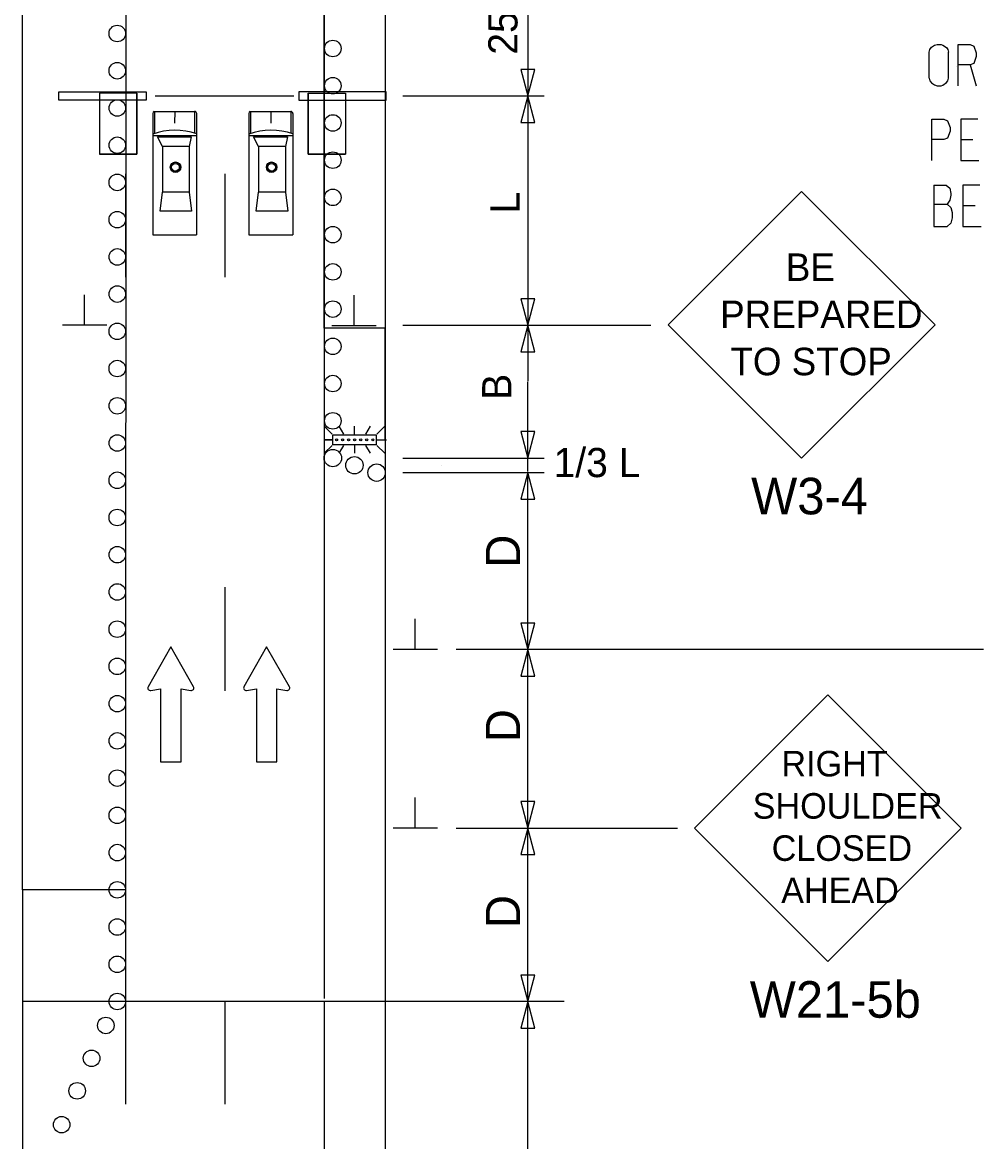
# Model space of a CAD drawing. Extents: x -1809 to 1557, y -1087 to 44.
# Drawn here: x -1476.9 to -1244.5, y -437.6 to -167 of the extents above; entities that cross this region are included whole.
import ezdxf

# ---------------------------------------------------------------- set-up
doc = ezdxf.new("R2010")
doc.units = 0
for name, color, linetype in [('BORDER', 7, 'Continuous'), ('Level 1', 7, 'Continuous'), ('Level 42', 7, 'Continuous'), ('MT_SCRATCH_LEVEL_A', 7, 'Continuous'), ('MT_SCRATCH_LEVEL_E', 7, 'Continuous'), ('MT_STAGE_1A_NOTES', 7, 'Continuous'), ('PAVT_EDGE_EX', 7, 'Continuous'), ('PAVT_EDGE_PR', 7, 'Continuous'), ('TRAFFIC_SIGNS_PR', 7, 'Continuous'), ('TYPICAL_EX', 7, 'Continuous'), ('TYPICAL_TEXT_DIMEN_EX', 7, 'Continuous'), ('TYPICAL_TEXT_DIMEN_PR', 7, 'Continuous')]:
    doc.layers.add(name, color=color, linetype=linetype)

msp = doc.modelspace()

# ---------------------------------------------------------------- linework, layer by layer
at = {"layer": 'BORDER'}
for p, q in [((-1403.94, -150.77), (-1403.94, -403.06)), ((-1451.94, -203.63), (-1451.94, -228.63)), ((-1427.94, -203.63), (-1427.94, -228.63)), ((-1451.94, -228.63), (-1451.94, -228.63)), ((-1427.94, -228.63), (-1427.94, -228.63)), ((-1451.94, -303.63), (-1451.94, -328.63)), ((-1427.94, -303.63), (-1427.94, -328.63)), ((-1451.94, -403.63), (-1451.94, -428.63)), ((-1427.94, -403.63), (-1427.94, -428.63)), ((-1403.94, -403.77), (-1403.94, -728.63))]:
    msp.add_line(p, q, dxfattribs=at)
at = {"layer": 'Level 1'}
for p, q in [((-1445.39, -189.02), (-1445.39, -218.4)), ((-1445.03, -188.56), (-1444.89, -188.56)), ((-1444.97, -188.56), (-1435.38, -188.56)), ((-1435.38, -188.56), (-1435.25, -188.56)), ((-1435.26, -188.56), (-1435.25, -188.56)), ((-1434.76, -189.11), (-1434.76, -218.4)), ((-1422.16, -189.02), (-1422.16, -218.4)), ((-1421.8, -188.56), (-1421.66, -188.56)), ((-1421.74, -188.56), (-1412.16, -188.56)), ((-1412.16, -188.56), (-1412.02, -188.56)), ((-1412.04, -188.56), (-1412.02, -188.56)), ((-1411.53, -189.11), (-1411.53, -218.4)), ((-1444.25, -194.72), (-1436.07, -194.72)), ((-1443.03, -197.08), (-1444.25, -194.72)), ((-1436.07, -194.72), (-1436.54, -197.08)), ((-1421.03, -194.72), (-1412.84, -194.72)), ((-1419.8, -197.08), (-1421.03, -194.72)), ((-1412.84, -194.72), (-1413.32, -197.08)), ((-1436.54, -197.08), (-1443.03, -197.08)), ((-1443.03, -197.08), (-1443.03, -208.13)), ((-1436.54, -197.08), (-1436.54, -208.13)), ((-1413.32, -197.08), (-1419.8, -197.08)), ((-1419.8, -197.08), (-1419.8, -208.13)), ((-1413.32, -197.08), (-1413.32, -208.13)), ((-1443.6, -212.66), (-1443.03, -208.13)), ((-1436.54, -208.13), (-1443.03, -208.13)), ((-1436.54, -208.13), (-1435.98, -212.66)), ((-1420.37, -212.66), (-1419.8, -208.13)), ((-1413.32, -208.13), (-1419.8, -208.13)), ((-1413.32, -208.13), (-1412.75, -212.66)), ((-1435.98, -212.66), (-1443.6, -212.66)), ((-1412.75, -212.66), (-1420.37, -212.66)), ((-1445.39, -218.4), (-1434.76, -218.4)), ((-1422.16, -218.4), (-1411.53, -218.4))]:
    msp.add_line(p, q, dxfattribs=at)
at = {"layer": 'Level 42'}
for p, q in [((-1380.84, -272.38), (-1380.84, -272.38)), ((-1375.61, -274.12), (-1375.61, -274.12)), ((-1370.25, -275.91), (-1370.25, -275.91))]:
    msp.add_line(p, q, dxfattribs=at)
at = {"layer": 'MT_SCRATCH_LEVEL_A'}
for p, q in [((-1476.89, -403.77), (-1476.89, -407.53)), ((-1476.89, -407), (-1476.89, -728.63))]:
    msp.add_line(p, q, dxfattribs=at)
msp.add_lwpolyline([(-1476.89, -61.73), (-1389.15, -61.73), (-1389.15, -240.97), (-1403.94, -240.97), (-1403.94, -150.77), (-1451.85, -150.77), (-1451.94, -376.78), (-1476.89, -376.78), (-1476.89, -61.73), (-1476.89, -61.73)], close=True, dxfattribs=at)
at = {"layer": 'MT_SCRATCH_LEVEL_E'}
for p, q in [((-1441.03, -318.01), (-1446.51, -327.66)), ((-1435.5, -327.66), (-1441.03, -318.01)), ((-1417.86, -318.01), (-1423.34, -327.66)), ((-1412.33, -327.66), (-1417.86, -318.01)), ((-1445.87, -328.57), (-1443.5, -328.15)), ((-1443.5, -328.15), (-1443.5, -345.83)), ((-1438.51, -345.83), (-1438.51, -328.15)), ((-1438.51, -328.15), (-1436.14, -328.57)), ((-1422.69, -328.57), (-1420.32, -328.15)), ((-1420.32, -328.15), (-1420.32, -345.83)), ((-1415.34, -345.83), (-1415.34, -328.15)), ((-1415.34, -328.15), (-1412.97, -328.57)), ((-1443.5, -345.83), (-1438.51, -345.83)), ((-1420.32, -345.83), (-1415.34, -345.83))]:
    msp.add_line(p, q, dxfattribs=at)
for centre, start, end in [((-1445.97, -327.96), 150.4248, 279.9638), ((-1436.05, -327.96), 260.0362, 29.7731), ((-1422.79, -327.96), 150.4248, 279.9638), ((-1412.87, -327.96), 260.0362, 29.7731)]:
    msp.add_arc(centre, 0.617, start, end, dxfattribs=at)
at = {"layer": 'MT_STAGE_1A_NOTES'}
for p, q in [((-1354.71, -61.78), (-1354.71, -253.81)), ((-1458.25, -184.14), (-1458.25, -198.89)), ((-1449.19, -184.14), (-1449.19, -198.89)), ((-1407.81, -184.14), (-1407.81, -198.89)), ((-1398.75, -184.14), (-1398.75, -198.89)), ((-1384.95, -184.82), (-1350.78, -184.82)), ((-1449.19, -198.89), (-1458.25, -198.89)), ((-1407.81, -198.89), (-1398.75, -198.89)), ((-1384.95, -240.29), (-1324.95, -240.29)), ((-1354.72, -275.65), (-1354.72, -253.96)), ((-1403.93, -267.96), (-1403.94, -267.96)), ((-1391.19, -267.96), (-1391.35, -267.96)), ((-1389.3, -267.96), (-1388.9, -267.96)), ((-1384.95, -272.38), (-1350.78, -272.38)), ((-1384.95, -275.91), (-1350.78, -275.91)), ((-1354.71, -318.56), (-1354.71, -275.97)), ((-1244.51, -318.67), (-1372.01, -318.67)), ((-1354.71, -361.86), (-1354.71, -319.27)), ((-1372.01, -361.86), (-1318.51, -361.86)), ((-1354.71, -404.81), (-1354.71, -362.22)), ((-1476.89, -376.78), (-1476.89, -403.77)), ((-1451.94, -376.78), (-1451.94, -403.63)), ((-1452.88, -403.77), (-1476.89, -403.77)), ((-1345.88, -403.77), (-1452.88, -403.77)), ((-1354.71, -449.91), (-1354.71, -404))]:
    msp.add_line(p, q, dxfattribs=at)
for points in [[(-1468.08, -183.83), (-1446.93, -183.83), (-1446.93, -185.82), (-1468.08, -185.82)], [(-1388.91, -183.83), (-1410.06, -183.83), (-1410.06, -185.82), (-1388.91, -185.82)], [(-1449.19, -184.14), (-1458.25, -184.14), (-1458.25, -198.89), (-1449.19, -198.89)], [(-1407.81, -184.14), (-1398.75, -184.14), (-1398.75, -198.89), (-1407.81, -198.89)]]:
    msp.add_lwpolyline(points, close=True, dxfattribs=at)
msp.add_lwpolyline([(-1403.94, -267.96), (-1403.93, -267.96), (-1402.04, -267.96), (-1401.88, -267.96), (-1401.88, -266.75), (-1391.35, -266.75), (-1391.35, -267.96), (-1391.19, -267.96), (-1389.3, -267.96), (-1389.15, -267.96), (-1389.15, -240.97), (-1403.94, -240.97), (-1403.94, -267.96)], dxfattribs=at)
at = {"layer": 'PAVT_EDGE_EX'}
for p, q in [((-1389.15, -150.83), (-1389.15, -407)), ((-1389.15, -407), (-1389.15, -728.63))]:
    msp.add_line(p, q, dxfattribs=at)
at = {"layer": 'PAVT_EDGE_PR'}
for p, q in [((-1444.96, -188.56), (-1444.96, -193.89)), ((-1440.07, -188.56), (-1440.09, -191.44)), ((-1435.25, -188.56), (-1435.25, -193.86)), ((-1421.73, -188.56), (-1421.73, -193.89)), ((-1416.84, -188.56), (-1416.86, -191.44)), ((-1412.02, -188.56), (-1412.02, -193.86)), ((-1445.39, -194.43), (-1434.78, -194.43)), ((-1422.16, -194.43), (-1411.55, -194.43))]:
    msp.add_line(p, q, dxfattribs=at)
for centre, radius in [((-1439.87, -202.07), 1.27), ((-1439.85, -202.08), 1.2), ((-1439.88, -202.07), 0.93), ((-1416.64, -202.07), 1.27), ((-1416.63, -202.08), 1.2), ((-1416.65, -202.07), 0.93)]:
    msp.add_circle(centre, radius, dxfattribs=at)
for centre, radius, start, end in [((-1444.91, -189.02), 0.469, 104.046, 184.9392), ((-1435.22, -189.03), 0.469, 350.5905, 93.3544), ((-1421.69, -189.02), 0.469, 104.046, 184.9392), ((-1411.99, -189.03), 0.469, 350.5905, 93.3544), ((-1440.04, -208.67), 15.57, 70.1557, 110.0625), ((-1416.81, -208.67), 15.57, 70.1557, 110.0625)]:
    msp.add_arc(centre, radius, start, end, dxfattribs=at)
at = {"layer": 'TRAFFIC_SIGNS_PR'}
for p, q in [((-1288.51, -207.92), (-1320.75, -240.16)), ((-1256.26, -240.16), (-1288.51, -207.92)), ((-1320.75, -240.16), (-1288.51, -272.41)), ((-1288.51, -272.41), (-1256.26, -240.16)), ((-1403.93, -264.71), (-1402.04, -266.6)), ((-1399.18, -266.6), (-1400.27, -264.71)), ((-1396.62, -266.6), (-1396.62, -264.71)), ((-1393.84, -266.6), (-1392.75, -264.71)), ((-1391.19, -266.6), (-1389.3, -264.71)), ((-1402.04, -267.96), (-1403.93, -267.96)), ((-1403.93, -271.21), (-1402.04, -269.32)), ((-1400.94, -267.96), (-1400.94, -267.96)), ((-1400.28, -271.22), (-1399.19, -269.32)), ((-1399.48, -267.96), (-1399.48, -267.96)), ((-1398.02, -267.96), (-1398.02, -267.96)), ((-1396.62, -269.32), (-1396.62, -271.22)), ((-1396.57, -267.96), (-1396.57, -267.96)), ((-1395.11, -267.96), (-1395.11, -267.96)), ((-1392.73, -271.22), (-1393.83, -269.32)), ((-1393.65, -267.96), (-1393.65, -267.96)), ((-1392.19, -267.96), (-1392.19, -267.96)), ((-1391.19, -267.96), (-1389.3, -267.96)), ((-1391.19, -269.32), (-1389.3, -271.22)), ((-1282.15, -329.61), (-1314.39, -361.86)), ((-1249.91, -361.86), (-1282.15, -329.61)), ((-1314.39, -361.86), (-1282.15, -394.1)), ((-1282.15, -394.1), (-1249.91, -361.86))]:
    msp.add_line(p, q, dxfattribs=at)
msp.add_lwpolyline([(-1391.35, -269.17), (-1401.88, -269.17), (-1401.88, -266.75), (-1391.35, -266.75)], close=True, dxfattribs=at)
for centre, radius in [((-1453.95, -169.74), 2), ((-1401.85, -173.36), 2), ((-1453.95, -178.74), 2), ((-1401.85, -182.36), 2), ((-1453.94, -187.75), 2), ((-1401.84, -191.36), 2), ((-1453.94, -196.74), 2), ((-1401.84, -200.36), 2), ((-1453.95, -205.74), 2), ((-1401.85, -209.36), 2), ((-1453.95, -214.74), 2), ((-1401.85, -218.37), 2), ((-1453.94, -223.75), 2), ((-1401.84, -227.37), 2), ((-1453.94, -232.74), 2), ((-1401.84, -236.37), 2), ((-1453.95, -241.74), 2), ((-1401.85, -245.37), 2), ((-1453.95, -250.74), 2), ((-1401.85, -254.37), 2), ((-1453.94, -259.75), 2), ((-1401.84, -263.38), 2), ((-1453.94, -268.75), 2), ((-1400.93, -267.96), 0.254), ((-1399.48, -267.96), 0.254), ((-1398.02, -267.96), 0.254), ((-1396.57, -267.96), 0.254), ((-1395.11, -267.96), 0.254), ((-1393.65, -267.96), 0.254), ((-1392.19, -267.96), 0.254), ((-1401.84, -272.38), 2.1), ((-1396.61, -274.12), 2.1), ((-1453.95, -277.75), 2), ((-1391.25, -275.91), 2.1), ((-1453.95, -286.75), 2), ((-1453.94, -295.75), 2), ((-1453.94, -304.75), 2), ((-1453.95, -313.75), 2), ((-1453.95, -322.75), 2), ((-1453.94, -331.76), 2), ((-1453.94, -340.76), 2), ((-1453.95, -349.76), 2), ((-1453.95, -358.76), 2), ((-1453.94, -367.77), 2), ((-1453.94, -376.77), 2), ((-1453.95, -385.77), 2), ((-1453.95, -394.77), 2), ((-1453.94, -403.77), 2), ((-1456.73, -409.56), 2), ((-1460.16, -417.5), 2), ((-1463.65, -425.37), 2), ((-1467.4, -433.55), 2)]:
    msp.add_circle(centre, radius, dxfattribs=at)
at = {"layer": 'TYPICAL_EX'}
for p, q in [((-1461.85, -240.29), (-1461.85, -232.9)), ((-1396.71, -240.41), (-1396.71, -233.01)), ((-1461.85, -240.29), (-1467.19, -240.29)), ((-1456.5, -240.29), (-1461.85, -240.29)), ((-1396.71, -240.41), (-1402.05, -240.41)), ((-1391.36, -240.41), (-1396.71, -240.41)), ((-1381.9, -318.67), (-1381.9, -311.28)), ((-1381.9, -318.67), (-1387.24, -318.67)), ((-1376.55, -318.67), (-1381.9, -318.67)), ((-1381.9, -361.86), (-1381.9, -354.46)), ((-1381.9, -361.86), (-1387.24, -361.86)), ((-1376.55, -361.86), (-1381.9, -361.86))]:
    msp.add_line(p, q, dxfattribs=at)
at = {"layer": 'TYPICAL_TEXT_DIMEN_EX'}
for p, q in [((-1257.5, -173.58), (-1257.14, -173.07)), ((-1257.14, -173.07), (-1256.42, -172.59)), ((-1256.42, -172.59), (-1255.73, -172.37)), ((-1255.73, -172.37), (-1254.79, -172.37)), ((-1254.79, -172.37), (-1254.33, -172.55)), ((-1254.33, -172.55), (-1253.45, -173.12)), ((-1253.45, -173.12), (-1253.14, -173.58)), ((-1250.68, -182.37), (-1250.68, -172.37)), ((-1250.68, -172.37), (-1247.76, -172.37)), ((-1247.76, -172.37), (-1246.89, -172.79)), ((-1246.89, -172.79), (-1246.27, -174.4)), ((-1257.65, -174.25), (-1257.5, -173.58)), ((-1257.65, -180.5), (-1257.65, -174.25)), ((-1253.14, -173.58), (-1252.99, -174.25)), ((-1252.99, -180.5), (-1252.99, -174.25)), ((-1246.27, -175.29), (-1246.89, -176.96)), ((-1246.27, -174.4), (-1246.27, -175.29)), ((-1251.07, -177.61), (-1251.07, -177.61)), ((-1247.76, -177.32), (-1250.68, -177.32)), ((-1246.89, -176.96), (-1247.76, -177.32)), ((-1247.76, -177.32), (-1246.27, -182.37)), ((-1257.65, -180.5), (-1257.5, -181.17)), ((-1257.5, -181.17), (-1257.14, -181.67)), ((-1253.45, -181.62), (-1253.14, -181.17)), ((-1253.14, -181.17), (-1252.99, -180.5)), ((-1257.14, -181.67), (-1256.42, -182.15)), ((-1256.42, -182.15), (-1255.73, -182.37)), ((-1255.73, -182.37), (-1254.79, -182.37)), ((-1254.79, -182.37), (-1254.33, -182.2)), ((-1254.33, -182.2), (-1253.45, -181.62)), ((-1257.01, -200.44), (-1257.01, -190.44)), ((-1257.01, -190.44), (-1254.09, -190.44)), ((-1257.01, -190.44), (-1257.01, -190.44)), ((-1254.09, -190.44), (-1253.22, -190.86)), ((-1253.22, -190.86), (-1252.6, -192.47)), ((-1245.93, -190.44), (-1250.01, -190.44)), ((-1250.01, -190.44), (-1250.01, -200.44)), ((-1252.6, -193.36), (-1253.22, -195.02)), ((-1252.6, -192.47), (-1252.6, -193.36)), ((-1254.09, -195.39), (-1257.01, -195.39)), ((-1253.22, -195.02), (-1254.09, -195.39)), ((-1247.09, -195.44), (-1250.01, -195.44)), ((-1250.01, -200.44), (-1245.63, -200.44)), ((-1256.51, -206.37), (-1253.59, -206.37)), ((-1256.51, -206.37), (-1256.51, -216.37)), ((-1253.59, -206.37), (-1252.7, -207.13)), ((-1252.7, -207.13), (-1252.42, -208.43)), ((-1245.42, -206.37), (-1249.51, -206.37)), ((-1249.51, -206.37), (-1249.51, -216.37)), ((-1256.51, -210.96), (-1253.3, -210.96)), ((-1252.7, -210.07), (-1253.3, -210.96)), ((-1253.3, -210.96), (-1252.42, -211.82)), ((-1252.42, -208.8), (-1252.7, -210.07)), ((-1252.42, -208.43), (-1252.42, -208.8)), ((-1252.42, -211.82), (-1252.09, -213.04)), ((-1252.09, -213.04), (-1252.09, -214.32)), ((-1246.59, -211.37), (-1249.51, -211.37)), ((-1256.51, -216.37), (-1253.3, -216.37)), ((-1252.42, -215.62), (-1253.3, -216.37)), ((-1252.09, -214.32), (-1252.42, -215.62)), ((-1249.51, -216.37), (-1245.13, -216.37))]:
    msp.add_line(p, q, dxfattribs=at)
at = {"layer": 'TYPICAL_TEXT_DIMEN_PR'}
for p, q in [((-1354.71, -178.42), (-1356.4, -178.42)), ((-1356.4, -178.42), (-1354.71, -184.82)), ((-1354.71, -184.82), (-1353.01, -178.42)), ((-1353.01, -178.42), (-1354.71, -178.42)), ((-1444.79, -184.82), (-1411.28, -184.82)), ((-1354.71, -184.82), (-1356.4, -191.23)), ((-1353.01, -191.23), (-1354.71, -184.82)), ((-1356.4, -191.23), (-1354.71, -191.23)), ((-1354.71, -191.23), (-1353.01, -191.23)), ((-1354.71, -233.85), (-1356.4, -233.85)), ((-1356.4, -233.85), (-1354.71, -240.26)), ((-1354.71, -240.26), (-1353.01, -233.85)), ((-1353.01, -233.85), (-1354.71, -233.85)), ((-1354.71, -240.26), (-1356.4, -246.66)), ((-1353.01, -246.66), (-1354.71, -240.26)), ((-1356.4, -246.66), (-1354.71, -246.66)), ((-1354.71, -246.66), (-1353.01, -246.66)), ((-1354.72, -265.97), (-1356.42, -265.97)), ((-1356.42, -265.97), (-1354.72, -272.38)), ((-1354.72, -272.38), (-1353.03, -265.97)), ((-1353.03, -265.97), (-1354.72, -265.97)), ((-1354.71, -275.91), (-1356.4, -282.31)), ((-1353.01, -282.31), (-1354.71, -275.91)), ((-1356.4, -282.31), (-1354.71, -282.31)), ((-1354.71, -282.31), (-1353.01, -282.31)), ((-1354.71, -312.27), (-1356.41, -312.27)), ((-1356.41, -312.27), (-1354.71, -318.67)), ((-1354.71, -318.67), (-1353.02, -312.27)), ((-1353.02, -312.27), (-1354.71, -312.27)), ((-1354.71, -318.67), (-1356.41, -325.08)), ((-1353.02, -325.08), (-1354.71, -318.67)), ((-1356.41, -325.08), (-1354.71, -325.08)), ((-1354.71, -325.08), (-1353.02, -325.08)), ((-1354.71, -355.45), (-1356.4, -355.45)), ((-1356.4, -355.45), (-1354.71, -361.86)), ((-1354.71, -361.86), (-1353.01, -355.45)), ((-1353.01, -355.45), (-1354.71, -355.45)), ((-1354.71, -361.86), (-1356.4, -368.26)), ((-1353.01, -368.26), (-1354.71, -361.86)), ((-1356.4, -368.26), (-1354.71, -368.26)), ((-1354.71, -368.26), (-1353.01, -368.26)), ((-1354.71, -397.37), (-1356.4, -397.37)), ((-1356.4, -397.37), (-1354.71, -403.77)), ((-1354.71, -403.77), (-1353.01, -397.37)), ((-1353.01, -397.37), (-1354.71, -397.37)), ((-1354.71, -403.77), (-1356.4, -410.18)), ((-1353.01, -410.18), (-1354.71, -403.77)), ((-1356.4, -410.18), (-1354.71, -410.18)), ((-1354.71, -410.18), (-1353.01, -410.18))]:
    msp.add_line(p, q, dxfattribs=at)

# ---------------------------------------------------------------- texts
at = {"layer": 'MT_STAGE_1A_NOTES'}
for s, height, rotation, p in [("250'", 7.054, 90, (-1357.2, -174.86)), ('L', 7.05, 90, (-1356.7, -213.26)), ('B', 7.05, 90, (-1358.69, -258.3)), ('1/3 L', 7.054, 360, (-1348.47, -276.99)), ('D', 8.25, 90, (-1356.6, -298.87)), ('D', 8.25, 90, (-1356.6, -341.06)), ('D', 8.25, 90, (-1356.6, -385.99))]:
    msp.add_text(s, height=height, rotation=rotation, dxfattribs=at).set_placement(p)
at = {"layer": 'TRAFFIC_SIGNS_PR'}
for s, height, p in [('BE', 6.65, (-1292.33, -229.56)), ('PREPARED', 6.65, (-1308.21, -240.96)), ('TO STOP', 6.65, (-1305.73, -252.36)), ('W3-4', 8.835, (-1300.71, -285.99)), ('RIGHT', 6.175, (-1293.39, -349.35)), ('SHOULDER', 6.175, (-1300.33, -359.56)), ('CLOSED', 6.175, (-1295.75, -369.77)), ('AHEAD', 6.175, (-1293.45, -379.98)), ('W21-5b', 8.835, (-1301.05, -407.69))]:
    msp.add_text(s, height=height, dxfattribs=at).set_placement(p)

doc.saveas('drawing.dxf')
